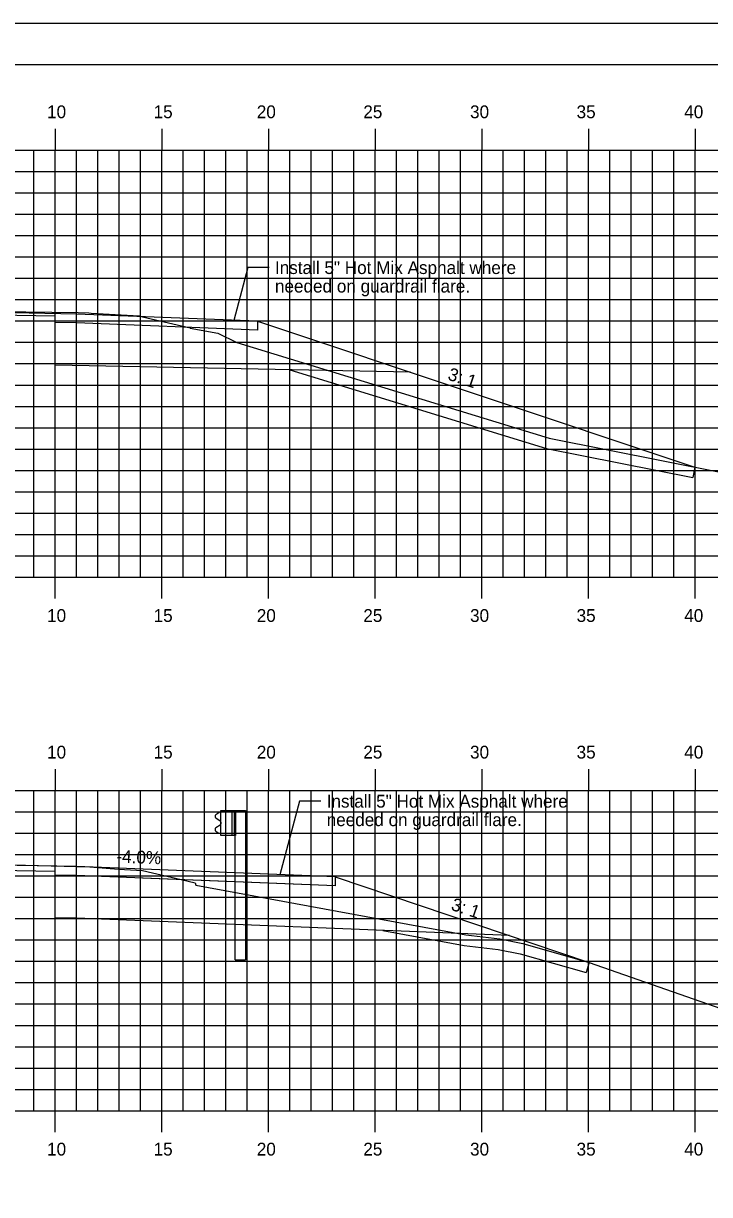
# Model space of a CAD drawing. Extents: x 2194502 to 2194968, y 863888 to 863998.
# Drawn here: x 2194707 to 2194739.2, y 863943.5 to 863998.4 of the extents above; entities that cross this region are included whole.
import ezdxf

# ---------------------------------------------------------------- set-up
doc = ezdxf.new("R2010")
doc.units = 0
for name, color, linetype in [('ANNOTATION', 7, 'Continuous'), ('BORDER', 7, 'Continuous'), ('D_Guardrail_Beam_Lt', 7, 'Continuous'), ('H_V ANNOTATION', 7, 'Continuous'), ('MAJOR', 7, 'Continuous'), ('MINOR', 7, 'Continuous'), ('PLOT BOUNDARY', 7, 'Continuous'), ('S_Roadway_Centerline', 7, 'Continuous'), ('TEMPLATE', 7, 'Continuous')]:
    doc.layers.add(name, color=color, linetype=linetype)

msp = doc.modelspace()

# ---------------------------------------------------------------- linework, layer by layer
at = {"layer": 'ANNOTATION'}
for points in [[(2194718.537, 863986.946), (2194717.537, 863986.946), (2194716.876, 863984.476)], [(2194720.961, 863961.946), (2194719.961, 863961.946), (2194719.038, 863958.5)]]:
    msp.add_lwpolyline(points, dxfattribs=at)
at = {"layer": 'BORDER'}
msp.add_lwpolyline([(2194623.499, 863891.446), (2194783.499, 863891.446), (2194783.499, 863996.446), (2194623.499, 863996.446)], close=True, dxfattribs=at)
at = {"layer": 'D_Guardrail_Beam_Lt'}
for p, q in [((2194716.178, 863961.408), (2194716.035, 863961.308)), ((2194716.035, 863961.165), (2194716.23, 863961.029)), ((2194716.268, 863961.429), (2194716.194, 863961.415)), ((2194716.268, 863961.512), (2194716.956, 863961.512)), ((2194716.268, 863960.346), (2194716.268, 863961.512)), ((2194716.789, 863961.512), (2194716.789, 863960.346)), ((2194716.893, 863961.512), (2194716.893, 863960.346)), ((2194716.956, 863961.512), (2194717.426, 863961.512)), ((2194716.956, 863961.512), (2194716.956, 863960.346)), ((2194717.426, 863961.512), (2194717.426, 863954.512)), ((2194716.23, 863960.83), (2194716.035, 863960.693)), ((2194716.264, 863960.964), (2194716.264, 863960.894)), ((2194716.035, 863960.55), (2194716.178, 863960.45)), ((2194716.194, 863960.444), (2194716.268, 863960.429)), ((2194716.956, 863960.346), (2194716.268, 863960.346)), ((2194716.935, 863954.512), (2194716.935, 863960.346)), ((2194716.935, 863954.512), (2194717.426, 863954.512))]:
    msp.add_line(p, q, dxfattribs=at)
for centre, major_axis, start_param, end_param in [((2194716.085, 863961.236), (-0.0877, 0), 5.323254, 7.243116), ((2194716.202, 863961.374), (-0.0417, 0), 4.907132, 5.323254), ((2194716.085, 863960.622), (-0.0877, 0), 5.323254, 7.243116), ((2194716.185, 863960.964), (0.0789, 0), 0, 0.959931), ((2194716.185, 863960.894), (0.0789, 0), 5.323254, 6.283185), ((2194716.202, 863960.484), (-0.0417, 0), 0.959931, 1.376053)]:
    msp.add_ellipse(centre, major_axis=major_axis, ratio=0.995501, start_param=start_param, end_param=end_param, dxfattribs=at)
at = {"layer": 'MAJOR'}
for p, q in [((2194708.499, 863993.448), (2194708.499, 863992.446)), ((2194713.499, 863993.448), (2194713.499, 863992.446)), ((2194718.499, 863993.448), (2194718.499, 863992.446)), ((2194723.499, 863993.448), (2194723.499, 863992.446)), ((2194728.499, 863993.448), (2194728.499, 863992.446)), ((2194733.499, 863993.448), (2194733.499, 863992.446)), ((2194738.499, 863993.448), (2194738.499, 863992.446)), ((2194628.499, 863992.446), (2194768.499, 863992.446)), ((2194628.499, 863992.446), (2194768.499, 863992.446)), ((2194708.499, 863972.446), (2194708.499, 863992.446)), ((2194713.499, 863972.446), (2194713.499, 863992.446)), ((2194718.499, 863972.446), (2194718.499, 863992.446)), ((2194723.499, 863972.446), (2194723.499, 863992.446)), ((2194728.499, 863972.446), (2194728.499, 863992.446)), ((2194733.499, 863972.446), (2194733.499, 863992.446)), ((2194738.499, 863972.446), (2194738.499, 863992.446)), ((2194628.499, 863987.446), (2194768.499, 863987.446)), ((2194628.499, 863982.446), (2194768.499, 863982.446)), ((2194628.499, 863977.446), (2194768.499, 863977.446)), ((2194628.499, 863972.446), (2194768.499, 863972.446)), ((2194708.499, 863971.444), (2194708.499, 863972.446)), ((2194713.499, 863971.444), (2194713.499, 863972.446)), ((2194718.499, 863971.444), (2194718.499, 863972.446)), ((2194723.499, 863971.444), (2194723.499, 863972.446)), ((2194728.499, 863971.444), (2194728.499, 863972.446)), ((2194733.499, 863971.444), (2194733.499, 863972.446)), ((2194738.499, 863971.444), (2194738.499, 863972.446)), ((2194708.499, 863963.448), (2194708.499, 863962.446)), ((2194713.499, 863963.448), (2194713.499, 863962.446)), ((2194718.499, 863963.448), (2194718.499, 863962.446)), ((2194723.499, 863963.448), (2194723.499, 863962.446)), ((2194728.499, 863963.448), (2194728.499, 863962.446)), ((2194733.499, 863963.448), (2194733.499, 863962.446)), ((2194738.499, 863963.448), (2194738.499, 863962.446)), ((2194628.499, 863962.446), (2194768.499, 863962.446)), ((2194708.499, 863947.446), (2194708.499, 863962.446)), ((2194713.499, 863947.446), (2194713.499, 863962.446)), ((2194718.499, 863947.446), (2194718.499, 863962.446)), ((2194723.499, 863947.446), (2194723.499, 863962.446)), ((2194728.499, 863947.446), (2194728.499, 863962.446)), ((2194733.499, 863947.446), (2194733.499, 863962.446)), ((2194738.499, 863947.446), (2194738.499, 863962.446)), ((2194628.499, 863957.446), (2194768.499, 863957.446)), ((2194628.499, 863952.446), (2194768.499, 863952.446)), ((2194628.499, 863947.446), (2194768.499, 863947.446)), ((2194708.499, 863946.444), (2194708.499, 863947.446)), ((2194713.499, 863946.444), (2194713.499, 863947.446)), ((2194718.499, 863946.444), (2194718.499, 863947.446)), ((2194723.499, 863946.444), (2194723.499, 863947.446)), ((2194728.499, 863946.444), (2194728.499, 863947.446)), ((2194733.499, 863946.444), (2194733.499, 863947.446)), ((2194738.499, 863946.444), (2194738.499, 863947.446))]:
    msp.add_line(p, q, dxfattribs=at)
at = {"layer": 'MINOR'}
for p, q in [((2194707.499, 863972.446), (2194707.499, 863992.446)), ((2194709.499, 863972.446), (2194709.499, 863992.446)), ((2194710.499, 863972.446), (2194710.499, 863992.446)), ((2194711.499, 863972.446), (2194711.499, 863992.446)), ((2194712.499, 863972.446), (2194712.499, 863992.446)), ((2194714.499, 863972.446), (2194714.499, 863992.446)), ((2194715.499, 863972.446), (2194715.499, 863992.446)), ((2194716.499, 863972.446), (2194716.499, 863992.446)), ((2194717.499, 863972.446), (2194717.499, 863992.446)), ((2194719.499, 863972.446), (2194719.499, 863992.446)), ((2194720.499, 863972.446), (2194720.499, 863992.446)), ((2194721.499, 863972.446), (2194721.499, 863992.446)), ((2194722.499, 863972.446), (2194722.499, 863992.446)), ((2194724.499, 863972.446), (2194724.499, 863992.446)), ((2194725.499, 863972.446), (2194725.499, 863992.446)), ((2194726.499, 863972.446), (2194726.499, 863992.446)), ((2194727.499, 863972.446), (2194727.499, 863992.446)), ((2194729.499, 863972.446), (2194729.499, 863992.446)), ((2194730.499, 863972.446), (2194730.499, 863992.446)), ((2194731.499, 863972.446), (2194731.499, 863992.446)), ((2194732.499, 863972.446), (2194732.499, 863992.446)), ((2194734.499, 863972.446), (2194734.499, 863992.446)), ((2194735.499, 863972.446), (2194735.499, 863992.446)), ((2194736.499, 863972.446), (2194736.499, 863992.446)), ((2194737.499, 863972.446), (2194737.499, 863992.446)), ((2194628.499, 863991.446), (2194768.499, 863991.446)), ((2194628.499, 863990.446), (2194768.499, 863990.446)), ((2194628.499, 863989.446), (2194768.499, 863989.446)), ((2194628.499, 863988.446), (2194768.499, 863988.446)), ((2194628.499, 863986.446), (2194768.499, 863986.446)), ((2194628.499, 863985.446), (2194768.499, 863985.446)), ((2194628.499, 863984.446), (2194768.499, 863984.446)), ((2194628.499, 863983.446), (2194768.499, 863983.446)), ((2194628.499, 863981.446), (2194768.499, 863981.446)), ((2194628.499, 863980.446), (2194768.499, 863980.446)), ((2194628.499, 863979.446), (2194768.499, 863979.446)), ((2194628.499, 863978.446), (2194768.499, 863978.446)), ((2194628.499, 863976.446), (2194768.499, 863976.446)), ((2194628.499, 863975.446), (2194768.499, 863975.446)), ((2194628.499, 863974.446), (2194768.499, 863974.446)), ((2194628.499, 863973.446), (2194768.499, 863973.446)), ((2194707.499, 863947.446), (2194707.499, 863962.446)), ((2194709.499, 863947.446), (2194709.499, 863962.446)), ((2194710.499, 863947.446), (2194710.499, 863962.446)), ((2194711.499, 863947.446), (2194711.499, 863962.446)), ((2194712.499, 863947.446), (2194712.499, 863962.446)), ((2194714.499, 863947.446), (2194714.499, 863962.446)), ((2194715.499, 863947.446), (2194715.499, 863962.446)), ((2194716.499, 863947.446), (2194716.499, 863962.446)), ((2194717.499, 863947.446), (2194717.499, 863962.446)), ((2194719.499, 863947.446), (2194719.499, 863962.446)), ((2194720.499, 863947.446), (2194720.499, 863962.446)), ((2194721.499, 863947.446), (2194721.499, 863962.446)), ((2194722.499, 863947.446), (2194722.499, 863962.446)), ((2194724.499, 863947.446), (2194724.499, 863962.446)), ((2194725.499, 863947.446), (2194725.499, 863962.446)), ((2194726.499, 863947.446), (2194726.499, 863962.446)), ((2194727.499, 863947.446), (2194727.499, 863962.446)), ((2194729.499, 863947.446), (2194729.499, 863962.446)), ((2194730.499, 863947.446), (2194730.499, 863962.446)), ((2194731.499, 863947.446), (2194731.499, 863962.446)), ((2194732.499, 863947.446), (2194732.499, 863962.446)), ((2194734.499, 863947.446), (2194734.499, 863962.446)), ((2194735.499, 863947.446), (2194735.499, 863962.446)), ((2194736.499, 863947.446), (2194736.499, 863962.446)), ((2194737.499, 863947.446), (2194737.499, 863962.446)), ((2194628.499, 863961.446), (2194768.499, 863961.446)), ((2194628.499, 863960.446), (2194768.499, 863960.446)), ((2194628.499, 863959.446), (2194768.499, 863959.446)), ((2194628.499, 863958.446), (2194768.499, 863958.446)), ((2194628.499, 863956.446), (2194768.499, 863956.446)), ((2194628.499, 863955.446), (2194768.499, 863955.446)), ((2194628.499, 863954.446), (2194768.499, 863954.446)), ((2194628.499, 863953.446), (2194768.499, 863953.446)), ((2194628.499, 863951.446), (2194768.499, 863951.446)), ((2194628.499, 863950.446), (2194768.499, 863950.446)), ((2194628.499, 863949.446), (2194768.499, 863949.446)), ((2194628.499, 863948.446), (2194768.499, 863948.446))]:
    msp.add_line(p, q, dxfattribs=at)
at = {"layer": 'PLOT BOUNDARY'}
msp.add_lwpolyline([(2194615.406, 863888.387), (2194785.406, 863888.387), (2194785.406, 863998.387), (2194615.406, 863998.387)], close=True, dxfattribs=at)
at = {"layer": 'S_Roadway_Centerline'}
for points in [[(2194666, 863982.427), (2194673.123, 863983.818), (2194674.81, 863984.278), (2194676.501, 863984.313), (2194683.393, 863984.628), (2194686.919, 863984.805), (2194687.224, 863984.838), (2194697.976, 863984.99), (2194698.502, 863984.991), (2194709.585, 863984.836), (2194710.081, 863984.824), (2194710.192, 863984.815), (2194712.436, 863984.681), (2194712.596, 863984.644), (2194714.834, 863984.124), (2194714.836, 863984.114), (2194716.134, 863983.876), (2194717.012, 863983.443), (2194731.656, 863978.954), (2194739.75, 863977.349), (2194747.963, 863976.289), (2194763.932, 863975.023), (2194764.031, 863975.023), (2194768.499, 863974.976)], [(2194670.976, 863957.344), (2194680.42, 863958.572), (2194680.878, 863958.638), (2194680.949, 863958.642), (2194685.157, 863958.786), (2194687.193, 863959.008), (2194692.54, 863959.083), (2194698.501, 863959.102), (2194704.085, 863959.024), (2194710.13, 863958.869), (2194711.477, 863958.767), (2194712.598, 863958.699), (2194714.403, 863958.284), (2194715.073, 863958.128), (2194715.095, 863958.006), (2194727.745, 863955.685), (2194729.344, 863955.492), (2194730.418, 863955.285), (2194733.533, 863954.397), (2194743.953, 863950.759), (2194747.523, 863950.45), (2194760.422, 863950.562), (2194768.499, 863950.601)]]:
    msp.add_lwpolyline(points, dxfattribs=at)
at = {"layer": 'TEMPLATE'}
for p, q in [((2194709.499, 863984.771), (2194698.499, 863984.991)), ((2194708.499, 863984.666), (2194698.499, 863984.866)), ((2194717.987, 863984.432), (2194709.499, 863984.771)), ((2194708.499, 863982.375), (2194708.499, 863984.666)), ((2194709.499, 863984.355), (2194708.499, 863984.375)), ((2194725.158, 863982.042), (2194708.499, 863982.375)), ((2194738.482, 863977.6), (2194738.385, 863977.11)), ((2194709.499, 863958.882), (2194698.499, 863959.102)), ((2194708.499, 863958.652), (2194698.499, 863958.852)), ((2194709.499, 863958.465), (2194708.499, 863958.485)), ((2194721.629, 863958.396), (2194709.499, 863958.882)), ((2194721.629, 863957.98), (2194709.499, 863958.465)), ((2194721.629, 863958.396), (2194733.533, 863954.397)), ((2194709.499, 863956.465), (2194708.499, 863956.485)), ((2194729.795, 863955.653), (2194709.499, 863956.465)), ((2194733.533, 863954.397), (2194733.396, 863953.916))]:
    msp.add_line(p, q, dxfattribs=at)
for points in [[(2194717.987, 863984.432), (2194717.987, 863984.015), (2194709.499, 863984.355)], [(2194717.987, 863984.432), (2194738.482, 863977.6)], [(2194719.509, 863982.155), (2194731.534, 863978.468), (2194738.385, 863977.11)], [(2194708.499, 863956.485), (2194708.499, 863958.652)], [(2194721.629, 863958.396), (2194721.629, 863957.98), (2194712.597, 863958.341)], [(2194723.853, 863955.891), (2194727.67, 863955.19), (2194729.267, 863954.997), (2194730.302, 863954.798), (2194733.396, 863953.916)]]:
    msp.add_lwpolyline(points, dxfattribs=at)

# ---------------------------------------------------------------- texts
at = {"layer": 'ANNOTATION'}
for s, p in [('Install 5" Hot Mix Asphalt where', (2194718.804, 863986.646)), ('needed on guardrail flare.', (2194718.804, 863985.779)), ('Install 5" Hot Mix Asphalt where', (2194721.228, 863961.646)), ('needed on guardrail flare.', (2194721.228, 863960.779))]:
    msp.add_text(s, height=0.6, dxfattribs=at).set_placement(p)
for s, rotation, p in [('3: 1', 341.5651, (2194726.863, 863981.709)), ('-4.0%', 357.7094, (2194711.366, 863959.074)), ('3: 1', 341.4293, (2194727.019, 863956.867))]:
    msp.add_text(s, height=0.6, rotation=rotation, dxfattribs=at).set_placement(p)
at = {"layer": 'H_V ANNOTATION'}
for s, p in [('10', (2194708.125, 863993.946)), ('15', (2194713.117, 863993.946)), ('20', (2194717.953, 863993.946)), ('25', (2194722.945, 863993.946)), ('30', (2194727.948, 863993.946)), ('35', (2194732.94, 863993.946)), ('40', (2194737.985, 863993.946)), ('10', (2194708.125, 863970.346)), ('15', (2194713.117, 863970.346)), ('20', (2194717.953, 863970.346)), ('25', (2194722.945, 863970.346)), ('30', (2194727.948, 863970.346)), ('35', (2194732.94, 863970.346)), ('40', (2194737.985, 863970.346)), ('10', (2194708.125, 863963.946)), ('15', (2194713.117, 863963.946)), ('20', (2194717.953, 863963.946)), ('25', (2194722.945, 863963.946)), ('30', (2194727.948, 863963.946)), ('35', (2194732.94, 863963.946)), ('40', (2194737.985, 863963.946)), ('10', (2194708.125, 863945.346)), ('15', (2194713.117, 863945.346)), ('20', (2194717.953, 863945.346)), ('25', (2194722.945, 863945.346)), ('30', (2194727.948, 863945.346)), ('35', (2194732.94, 863945.346)), ('40', (2194737.985, 863945.346))]:
    msp.add_text(s, height=0.6, dxfattribs=at).set_placement(p)

doc.saveas('drawing.dxf')
